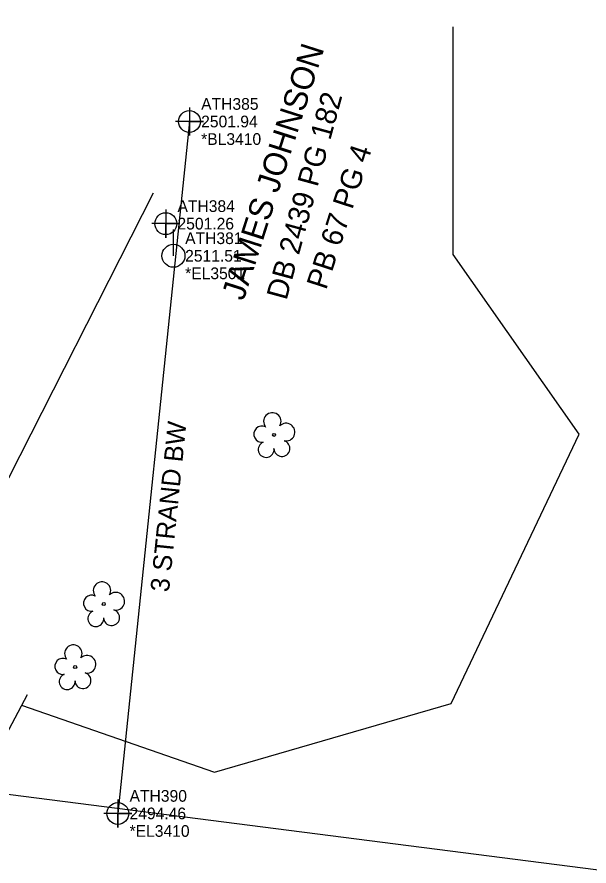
# Model space of a CAD drawing. Extents: x 983976 to 986421, y 758828 to 761458.
# Drawn here: x 984979.4 to 985101.7, y 760189.2 to 760370.7 of the extents above; entities that cross this region are included whole.
import ezdxf

# ---------------------------------------------------------------- set-up
doc = ezdxf.new("R2010")
doc.units = 0
for name, color, linetype in [('Exist Other Culture Fence Line', 7, 'Continuous'), ('Exist Other Culture Fence Line Cogo Comment', 7, 'Continuous'), ('Exist Other Culture Fence Line Cogo Elevation', 7, 'Continuous'), ('Exist Other Culture Fence Line Cogo Number', 7, 'Continuous'), ('Exist Other Culture Fence Line Cogo Point CELL', 7, 'Continuous'), ('Exist Other Culture Fence Line Text', 7, 'Continuous'), ('Exist Property Deed Book Text', 7, 'Continuous'), ('Exist Property Line', 7, 'Continuous'), ('Exist Property Owner Text', 7, 'Continuous'), ('Exist Right of Way Line', 7, 'Continuous'), ('Exist Utilities Power Pole CELL', 7, 'Continuous'), ('Exist Utilities Power Pole Cogo Comment', 7, 'Continuous'), ('Exist Utilities Power Pole Cogo Elevation', 7, 'Continuous'), ('Exist Utilities Power Pole Cogo Number', 7, 'Continuous'), ('Exist Vegetation Tree CELL', 7, 'Continuous'), ('Exist Vegetation Woods Line', 7, 'Continuous')]:
    doc.layers.add(name, color=color, linetype=linetype)

msp = doc.modelspace()

# ---------------------------------------------------------------- linework, layer by layer
at = {"layer": 'Exist Other Culture Fence Line'}
msp.add_line((985016.3, 760348.38), (985001, 760200.45), dxfattribs=at)
at = {"layer": 'Exist Other Culture Fence Line Cogo Point CELL'}
for points in [[(985016.3, 760351.38), (985016.3, 760345.38), (985016.3, 760348.38), (985019.3, 760348.38), (985013.3, 760348.38)], [(985011.24, 760329.54), (985011.24, 760323.54), (985011.24, 760326.54), (985014.24, 760326.54), (985008.24, 760326.54)], [(985001, 760203.45), (985001, 760197.45), (985001, 760200.45), (985004, 760200.45), (984998, 760200.45)]]:
    msp.add_lwpolyline(points, dxfattribs=at)
for centre in [(985016.3, 760348.38), (985011.24, 760326.54), (985001, 760200.45)]:
    msp.add_circle(centre, 2.34, dxfattribs=at)
at = {"layer": 'Exist Property Line'}
msp.add_line((985486.15, 760139.25), (984928.03, 760210.83), dxfattribs=at)
at = {"layer": 'Exist Right of Way Line'}
msp.add_arc((985398.11, 760220.4), 447.46, 152.3367, 165.2561, dxfattribs=at)
at = {"layer": 'Exist Utilities Power Pole CELL'}
for q in [(985012.88, 760325.29), (985012.88, 760319.67)]:
    msp.add_line((985012.88, 760319.67), q, dxfattribs=at)
msp.add_circle((985012.88, 760319.67), 2.45, dxfattribs=at)
at = {"layer": 'Exist Vegetation Tree CELL'}
for p, q in [((985034.39, 760281.38), (985034.39, 760281.38)), ((984997.99, 760245.22), (984997.99, 760245.22)), ((984991.87, 760231.74), (984991.87, 760231.74))]:
    msp.add_line(p, q, dxfattribs=at)
for centre in [(985034.39, 760281.38), (984997.99, 760245.22), (984991.87, 760231.74)]:
    msp.add_circle(centre, 0.326, dxfattribs=at)
for centre, radius, start, end in [((985034.01, 760284.25), 1.86, 330.1651, 219.7134), ((985031.79, 760281.53), 1.73, 62.6636, 279.3457), ((985036.94, 760281.97), 1.9, 257.1011, 134.1999), ((985032.69, 760278.26), 1.69, 111.5671, 6.231), ((985036.06, 760278.48), 1.7, 181.2822, 74.56), ((984997.61, 760248.09), 1.86, 330.1651, 219.7134), ((984995.39, 760245.38), 1.73, 62.6636, 279.3457), ((985000.54, 760245.81), 1.9, 257.1011, 134.1999), ((984996.29, 760242.1), 1.69, 111.5671, 6.231), ((984999.66, 760242.32), 1.7, 181.2822, 74.56), ((984991.48, 760234.61), 1.86, 330.1651, 219.7134), ((984994.41, 760232.33), 1.9, 257.1011, 134.1999), ((984989.26, 760231.89), 1.73, 62.6636, 279.3457), ((984990.16, 760228.62), 1.69, 111.5671, 6.231), ((984993.54, 760228.84), 1.7, 181.2822, 74.56)]:
    msp.add_arc(centre, radius, start, end, dxfattribs=at)
at = {"layer": 'Exist Vegetation Woods Line'}
msp.add_line((985008.58, 760333.06), (984967.64, 760252.53), dxfattribs=at)
for points in [[(984980.42, 760223.56), (985021.63, 760209.24), (985072.26, 760223.95), (985099.62, 760281.56), (985072.67, 760319.96), (985072.67, 760368.61)], [(984902.49, 760095.82), (984939.65, 760146.48), (984981.66, 760225.9)]]:
    msp.add_lwpolyline(points, dxfattribs=at)

# ---------------------------------------------------------------- texts
at = {"layer": 'Exist Other Culture Fence Line Cogo Comment'}
for s, p in [('*BL3410', (985018.8, 760343.38)), ('*EL3410', (985003.5, 760195.45))]:
    msp.add_text(s, height=2.5, dxfattribs=at).set_placement(p)
at = {"layer": 'Exist Other Culture Fence Line Cogo Elevation'}
for s, p in [('2501.94', (985018.8, 760347.13)), ('2501.26', (985013.74, 760325.29)), ('2494.46', (985003.5, 760199.2))]:
    msp.add_text(s, height=2.5, dxfattribs=at).set_placement(p)
at = {"layer": 'Exist Other Culture Fence Line Cogo Number'}
for s, p in [('ATH385', (985018.8, 760350.88)), ('ATH384', (985013.74, 760329.04)), ('ATH390', (985003.5, 760202.95))]:
    msp.add_text(s, height=2.5, dxfattribs=at).set_placement(p)
at = {"layer": 'Exist Other Culture Fence Line Text'}
msp.add_text('3 STRAND BW', height=4, rotation=84.0949, dxfattribs=at).set_placement((985011.91, 760247.65))
at = {"layer": 'Exist Property Deed Book Text'}
for s, rotation, p in [('DB 2439 PG 182', 74.7265, (985037.04, 760310.01)), ('PB 67 PG 4', 71.9706, (985045.5, 760312.23))]:
    msp.add_text(s, height=4.5, rotation=rotation, dxfattribs=at).set_placement(p)
at = {"layer": 'Exist Property Owner Text'}
msp.add_text('JAMES JOHNSON', height=5, rotation=72.2647, dxfattribs=at).set_placement((985027.86, 760309.86))
at = {"layer": 'Exist Utilities Power Pole Cogo Comment'}
msp.add_text('*EL3501', height=2.5, dxfattribs=at).set_placement((985015.38, 760314.67))
at = {"layer": 'Exist Utilities Power Pole Cogo Elevation'}
msp.add_text('2511.51', height=2.5, dxfattribs=at).set_placement((985015.38, 760318.42))
at = {"layer": 'Exist Utilities Power Pole Cogo Number'}
msp.add_text('ATH381', height=2.5, dxfattribs=at).set_placement((985015.38, 760322.17))

doc.saveas('drawing.dxf')
